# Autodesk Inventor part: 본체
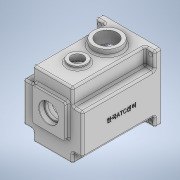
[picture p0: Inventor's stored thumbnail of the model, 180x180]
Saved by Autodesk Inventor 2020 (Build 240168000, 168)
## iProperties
Created: 2022-01
Part Number: 본체
Material: 일반
Document SubType Name: Modeling
Designer: user
Density: 1 g/cm^3
Appearance: 기본값
Author: user
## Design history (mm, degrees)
sketch "스케치1"
  geometry: L1 (-49, 55)-(49, 55); L2 (49, 55)-(49, -55); L3 (49, -55)-(-49, -55); L4 (-49, -55)-(-49, 55); L5 (-49, 55)-(49, -55); L6 (49, 55)-(-49, -55); 1 further point
  constraints: 12 end point, 2 midpoint, 2 parallel, 1 horizontal, 1 perpendicular
  dimensions: "d0" = 98 distance of L2.end L3.end; "d1" = 110 distance of L1.end L2.end
extrude "돌출1" new body sketch "스케치1" distance "d2" = 10; taper "d3" = 0 deg
sketch "스케치2"
  geometry: L1 (49, 55)-(-49, 55) reference; L2 (-49, 55)-(-33, 55); L3 (-33, 55)-(-33, 28); L4 (-33, 28)-(-49, 28); L5 (-49, 28)-(-49, 55); L6 (49, -55)-(49, 55) reference; L7 (49, 55)-(33, 55); L8 (33, 55)-(33, 28); L9 (33, 28)-(49, 28); L10 (49, 28)-(49, 55); L11 (-49, -55)-(49, -55) reference; L12 (-49, -55)-(-33, -55); L13 (-33, -55)-(-33, -38); L14 (-33, -38)-(-49, -38); L15 (-49, -38)-(-49, -55); L16 (49, -55)-(33, -55); L17 (33, -55)-(33, -38); L18 (33, -38)-(49, -38); L19 (49, -38)-(49, -55); L20 (-49, 28)-(-49, -38); L21 (-49, 55)-(-49, -55) reference; 6 further points
  constraints: 34 end point, 8 parallel, 4 horizontal, 4 perpendicular, 2 point on line, 1 collinear
  dimensions: "d10" = 16 distance between parallel lines of L5 L3; "d11" = 16 distance between parallel lines of L10 L8; "d12" = 16 distance between parallel lines of L15 L13; "d13" = 27 distance of L9.end L1.start; "d14" = 27 distance of L4.end L1.end; "d15" = 17 distance of L14.end L11.start
extrude "돌출2" join sketch "스케치2" distance "d16" = 120; taper "d17" = 0 deg
sketch "스케치3"
  geometry: L1 (-27, 33)-(27, 33); L2 (27, 33)-(27, -21); L3 (27, -21)-(-27, -21); L4 (-27, -21)-(-27, 33); L5 (-27, 33)-(27, -21); L6 (27, 33)-(-27, -21); L7 (-33, -55)-(33, -55) reference; 2 further points
  constraints: 12 end point, 2 midpoint, 2 parallel, 1 horizontal, 1 perpendicular
  dimensions: "d18" = 61 distance from line of L7 point (0, 6); "d19" = 54 distance of L1.start L1.end; "d20" = 54 distance of L3.end L1.start; "d21" = 27 distance from line of point (0, 0) L4
extrude "돌출3" join sketch "스케치3" distance "d22" = 7; taper "d23" = 0 deg
sketch "스케치5"
  geometry: L1 (49, -55)-(-49, -55) reference; L2 (49, 55)-(49, -55) reference; L3 (0, -5)-(0, 45); L4 (0, 45)-(-23, 45); L5 (-23, 45)-(-23, -5); L6 (-23, -5)-(0, -5); L7 (-23, 45)-(23, 45); L8 (23, 45)-(23, -5); L9 (23, -5)-(-23, -5); L10 (-23, -5)-(-23, 45); C1 r 42 at (0, -5); 3 further points
  constraints: 16 end point, 4 perpendicular, 2 parallel, 1 centre point, 1 horizontal, 1 vertical
  dimensions: "d25" = 84 diameter of C1; "d26" = 50 distance from line of L1 L3.start; "d27" = 49 distance from line of L3.start L2; "d28" = 50 distance of L3.start L3.end; "d29" = 23 distance of L3.end L4.end; "d30" = 46 distance of L8.end L9.end; "d31" = 50 distance of L7.end L8.end
extrude "돌출4" cut sketch "스케치5" distance "d32" = 121; taper "d33" = 0 deg
sketch "스케치7"
  geometry: L1 (23, 45)-(23, 30.143) reference; L2 (-23, 45)-(23, 45) reference; L3 (-23, 30.143)-(-23, 45) reference; L4 (26, 31.729)-(26, 48); L5 (26, 48)-(-26, 48); L6 (-26, 48)-(-26, 31.729); A1 r 42 centre (0, -5) between (-23, 30.143) and (23, 30.143) reference; A2 r 45 centre (0, -5) between (-26, 31.729) and (26, 31.729); 1 further point
  constraints: 6 end point, 2 point on circle, 1 centre point, 3 other
  dimensions: "d38" = 3 radial gap between concentric circles of A1 A2
extrude "돌출5" cut sketch "스케치7" distance "d39" = 9; taper "d40" = 0 deg
sketch "스케치8" dims "d41" = 72
  geometry: L1 (36, -9)-(45.904, -9); L2 (45.904, -9)-(45.508, -1); L3 (45.508, -1)-(36, -1); A1 r 42 centre (0, -5) between (-23, 30.143) and (23, 30.143) reference; A2 r 4 centre (36, -5) between (36, -1) and (36, -9); 2 further points
  constraints: 6 end point, 2 horizontal alignment, 2 point on circle, 2 tangent, 1 centre point, 1 coincident, 1 horizontal, 1 parallel, 2 other
  dimensions: "d42" = 8 diameter of A2
extrude "돌출6" join sketch "스케치8" stored distance "d43" = 9; taper "d44" = 0 deg
sketch "스케치9"
  geometry: 1 further point
sketch "스케치10"
  geometry: L1 (-36, -9)-(-41.809, -9) reference; L2 (41.809, -9)-(36, -9) reference; L3 (36, -1)-(41.809, -1) reference; L4 (23, 45)-(23, 30.143) reference; L5 (-23, 45)-(23, 45) reference; L6 (-23, 30.143)-(-23, 45) reference; L7 (-41.809, -1)-(-36, -1) reference; L8 (0, -5)-(0, -25); L9 (0, -5)-(0, 6); C1 r 15 at (0, -25); C2 r 21 at (0, 6); A1 r 42 centre (0, -5) between (-41.809, -9) and (41.809, -9) reference; A2 r 4 centre (36, -5) between (36, -1) and (36, -9) reference; A3 r 42 centre (0, -5) between (41.809, -1) and (23, 30.143) reference; A4 r 42 centre (0, -5) between (-23, 30.143) and (-41.809, -1) reference; A5 r 4 centre (-36, -5) between (-36, -9) and (-36, -1) reference; 3 further points
  constraints: 4 end point, 2 centre point, 2 coincident, 2 vertical
  dimensions: "d45" = 20 distance of L8.start L8.end; "d46" = 30 diameter of C1; "d47" = 11 distance of L8.start L9.end; "d48" = 42 diameter of C2
extrude "돌출7" join sketch "스케치10" distance "d49" = 7; taper "d50" = 0 deg
sketch "스케치11"
  geometry: L1 (49, -89)-(49, 0); L2 (98, 0)-(0, 0) reference; C1 r 22.5 at (49, -40); C2 r 15 at (49, -89); 1 further point
  constraints: 2 centre point, 2 end point, 1 midpoint, 1 point on line, 1 vertical
  dimensions: "d51" = 45 diameter of C1; "d52" = 30 diameter of C2; "d53" = 40 distance of C1.centre L1.end; "d54" = 49 distance of L1.start C1.centre
extrude "돌출8" join sketch "스케치11" distance "d55" = 5; taper "d56" = 0 deg
sketch "스케치12"
  geometry: C1 r 15 at (0, 0) reference; C2 r 10 at (0, 0); 1 further point
  constraints: 1 centre point, 1 coincident
  dimensions: "d57" = 20 diameter of C2
extrude "돌출9" cut sketch "스케치12" distance "d58" = 26.25; taper "d59" = 0 deg
sketch "스케치14"
  geometry: C1 r 10 at (23, -32) reference; C2 r 15 at (23, -32); 1 further point
  constraints: 1 centre point, 1 coincident
  dimensions: "d67" = 30 diameter of C2
extrude "돌출10" cut sketch "스케치14" distance "d68" = 5; taper "d69" = 0 deg
chamfer "모따기1" distance "d70" = 1; stored, may be unused: second distance "d71" = 2, angle "d72" = 45 deg
sketch "스케치15"
  geometry: L1 (27, 33)-(-27, 33) reference; L2 (0, 33)-(0, 6); C1 r 14 at (0, 6); 1 further point
  constraints: 2 end point, 1 centre point, 1 coincident, 1 midpoint, 1 vertical
  dimensions: "d73" = 27 distance of L2.start L2.end; "d74" = 28 diameter of C1
extrude "돌출11" cut sketch "스케치15" distance "d75" = 88.75; taper "d76" = 0 deg
sketch "스케치16"
  geometry: C1 r 14 at (0, 6) reference; C2 r 16 at (0, 6); 1 further point
  constraints: 1 centre point, 1 coincident
  dimensions: "d77" = 32 diameter of C2
extrude "돌출12" cut sketch "스케치16" distance "d78" = 8.3; taper "d79" = 0 deg
fillet "모깎기1" dims "d80" = 0.3
chamfer "모따기2" distance "d81" = 0.8; stored, may be unused: second distance "d82" = 2, angle "d83" = 30 deg
sketch "스케치18"
  geometry: C1 r 17.5 at (0, 6); A1 r 21 centre (0, 6) between (8.978, -12.984) and (-8.978, -12.984) reference; 1 further point
  constraints: 1 centre point, 1 coincident
  dimensions: "d84" = 35 diameter of C1
extrude "돌출13" cut sketch "스케치18" distance "d85" = 10; taper "d86" = 0 deg
fillet "모깎기2" dims "d87" = 0.3
sketch "스케치20"
  geometry: C1 r 9.5 at (0, -25); A1 r 15 centre (0, -25) between (-8.978, -12.984) and (8.978, -12.984) reference; 1 further point
  constraints: 1 centre point, 1 coincident
  dimensions: "d88" = 19 diameter of C1
extrude "돌출14" cut sketch "스케치20" distance "d89" = 10; taper "d90" = 0 deg
sketch "스케치21"
  geometry: C1 r 9.5 at (0, -25) reference; C2 r 11 at (0, -25); 1 further point
  constraints: 1 centre point, 1 coincident
  dimensions: "d91" = 22 diameter of C2
extrude "돌출15" cut sketch "스케치21" distance "d92" = 7; taper "d93" = 0 deg
fillet "모깎기3" dims "d94" = 3
fillet "모깎기4" dims "d95" = 0.3
chamfer "모따기3" distance "d96" = 1; stored, may be unused: second distance "d97" = 2, angle "d98" = 30 deg
chamfer "모따기4" distance "d99" = 1; stored, may be unused: second distance "d100" = 2, angle "d101" = 30 deg
fillet "모깎기5" dims "d102" = 3
fillet "모깎기6" dims "d103" = 3
fillet "모깎기7" dims "d104" = 3
fillet "모깎기8" dims "d105" = 6
fillet "모깎기9" dims "d106" = 3
fillet "모깎기10" dims "d107" = 3
fillet "모깎기11" dims "d108" = 3
fillet "모깎기12" dims "d109" = 3
chamfer "모따기5" distance "d110" = 1; stored, may be unused: second distance "d111" = 2, angle "d112" = 30 deg
sketch "스케치23"
  geometry: C1 r 36 at (0, -5); A1 r 46 centre (0, -5) between (-27.792, 31.655) and (27.792, 31.655) reference; A2 r 4 centre (-36, -5) between (-36, -9) and (-36, -1) reference; 2 further points
  constraints: 2 coincident, 1 centre point
  dimensions: "d113" = 72 diameter of C1
hole "구멍2" sketch "스케치23" at (-36, -5) diameter "d114" = 3.242; stored, may be unused: countersink angle "d118" = 90 deg, drill point angle "d120" = 118 deg; dims "d115" = 7, "d116" = 4, "d117" = 2, "d119" = 9
sketch "스케치24"
  geometry: L1 (-49, 55)-(49, 55) reference; L2 (-49, -55)-(-49, 55) reference; C1 r 3.5 at (-42, 48); 1 further point
  constraints: 1 centre point
  dimensions: "d121" = 7 diameter of C1; "d122" = 7 distance from line of L1 C1.centre; "d123" = 7 distance from line of C1.centre L2
extrude "돌출16" cut sketch "스케치24" distance "d124" = 30.5; taper "d125" = 0 deg
fillet "모깎기13" dims "d132" = 3
fillet "모깎기14" dims "d133" = 3
fillet "모깎기15" dims "d134" = 3
fillet "모깎기16" dims "d135" = 3
fillet "모깎기17" dims "d136" = 3
fillet "모깎기18" dims "d137" = 3
fillet "모깎기19" dims "d138" = 3
fillet "모깎기20" dims "d139" = 3
sketch "스케치25"
  geometry: L1 (-130, 104)-(-130, 83) reference; L2 (-13, 80)-(-127, 80) reference; 2 further points
  constraints: 1 other
  dimensions: "d140" = 65 distance from line of point (-65, 47) L1; "d141" = 33 distance from line of point (-65, 47) L2
feature "엠보싱1" sketch "스케치25" dims "d142" = 0.5, "d143" = 0
sketch "스케치26"
  geometry: C1 r 22.5 at (0, 0); 1 further point
  constraints: 1 centre point
extrude "돌출17" join sketch "스케치26" distance "d144" = 5; taper "d145" = 0 deg
sketch "스케치27"
  geometry: C1 r 22.5 at (0, 0) reference; 2 further points
  constraints: 1 coincident
hole "구멍3" sketch "스케치27" at (0, 0) diameter "d146" = 33.376; stored, may be unused: countersink angle "d150" = 90 deg, drill point angle "d152" = 0 deg; dims "d147" = 70, "d148" = 4, "d149" = 2, "d151" = 77.3
node "솔리드1"
mirror "미러1"
mirror "미러2"
pattern_linear "직사각형 패턴1" dims "d128" = 84, "d131" = 96
node "투영된 루프2"
node "투영된 루프3"
feature "A9D066F2-1C7D-4E18-AEED-F7BC21143FA4" dims "d114" = 3.242, "d115" = 7, "d116" = 4, "d117" = 2, "d118" = 90 deg, "d119" = 9, "d120" = 118 deg
